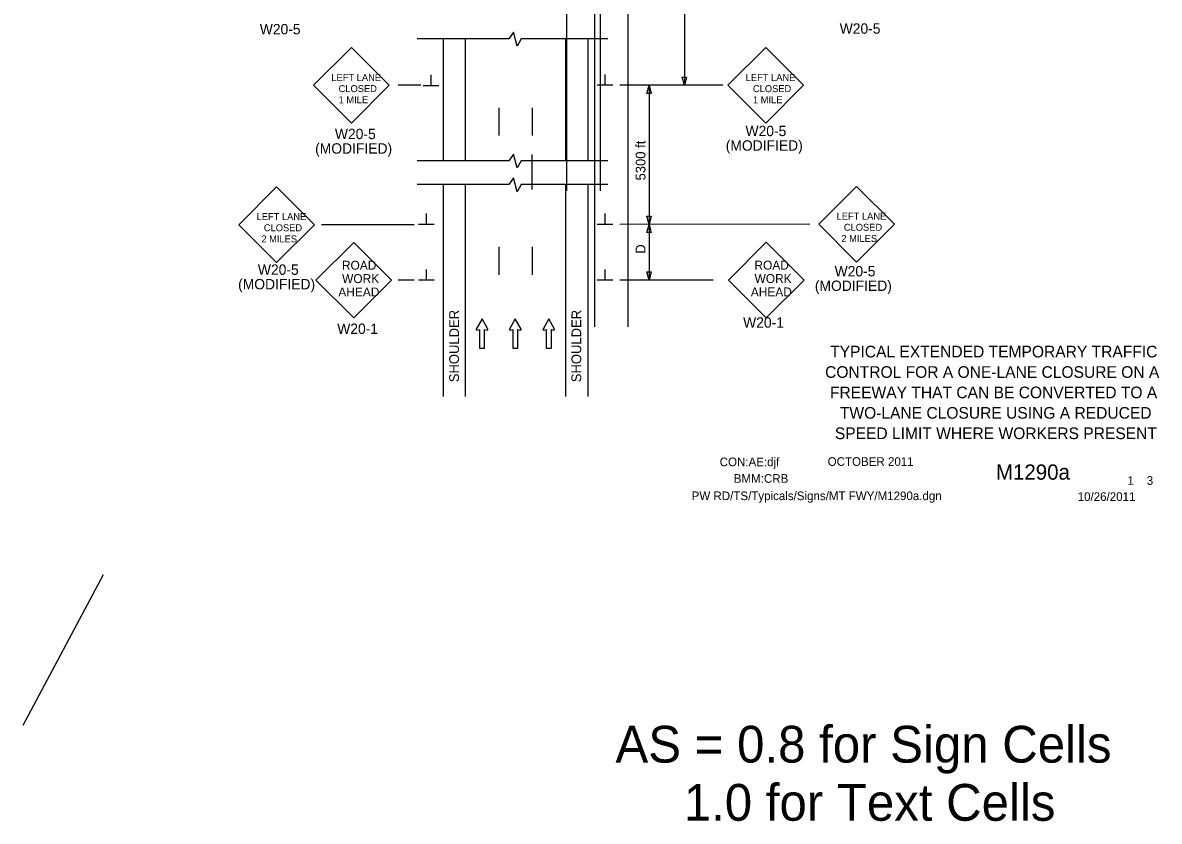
# Model space of a CAD drawing. Extents: x 16590 to 19504, y 5703 to 6974.
# Drawn here: x 16590 to 17407, y 5703 to 6277 of the extents above; entities that cross this region are included whole.
import ezdxf

# ---------------------------------------------------------------- set-up
doc = ezdxf.new("R2010")
doc.units = 0
for name, color, linetype in [('ALI_LEGAL_EX', 7, 'Continuous'), ('BORDER', 7, 'Continuous'), ('BORDER_SIGNAL_WO', 7, 'Continuous'), ('MT_SCRATCH_LEVEL_E', 7, 'Continuous'), ('PAVT_EDGE_EX', 7, 'Continuous'), ('TRAFFIC_SIGNS_PR', 7, 'Continuous'), ('TYPICAL_TEXT_DIMEN_PR', 7, 'Continuous')]:
    doc.layers.add(name, color=color, linetype=linetype)

msp = doc.modelspace()

# ---------------------------------------------------------------- linework, layer by layer
at = {"layer": 'ALI_LEGAL_EX'}
for p, q in [((16980.68, 6974.12), (16980.68, 6155.98)), ((17004.68, 6974.12), (17004.68, 6155.98)), ((17000.61, 6922.21), (17000.61, 6058.3)), ((17024.61, 6922.21), (17024.61, 6058.3))]:
    msp.add_line(p, q, dxfattribs=at)
for points in [[(16931.89, 6215.64), (16931.89, 6195.69)], [(16955.89, 6215.64), (16955.89, 6195.69)], [(16955.89, 6156.97), (16955.89, 6181.97)], [(16931.89, 6115.64), (16931.89, 6095.69)], [(16955.89, 6115.64), (16955.89, 6095.69)]]:
    msp.add_lwpolyline(points, dxfattribs=at)
at = {"layer": 'MT_SCRATCH_LEVEL_E'}
for p, q in [((16919.89, 6063.87), (16915.78, 6056.63)), ((16924.03, 6056.63), (16919.89, 6063.87)), ((16943.79, 6063.87), (16939.68, 6056.63)), ((16947.94, 6056.63), (16943.79, 6063.87)), ((16967.84, 6063.87), (16963.73, 6056.63)), ((16971.99, 6056.63), (16967.84, 6063.87)), ((16916.26, 6055.95), (16918.04, 6056.26)), ((16918.04, 6056.26), (16918.04, 6043.01)), ((16921.78, 6043.01), (16921.78, 6056.26)), ((16921.78, 6056.26), (16923.56, 6055.95)), ((16940.16, 6055.95), (16941.94, 6056.26)), ((16941.94, 6056.26), (16941.94, 6043.01)), ((16945.68, 6043.01), (16945.68, 6056.26)), ((16945.68, 6056.26), (16947.46, 6055.95)), ((16964.22, 6055.95), (16965.99, 6056.26)), ((16965.99, 6056.26), (16965.99, 6043.01)), ((16969.73, 6043.01), (16969.73, 6056.26)), ((16969.73, 6056.26), (16971.51, 6055.95)), ((16918.04, 6043.01), (16921.78, 6043.01)), ((16941.94, 6043.01), (16945.68, 6043.01)), ((16965.99, 6043.01), (16969.73, 6043.01))]:
    msp.add_line(p, q, dxfattribs=at)
for centre, start, end in [((16916.18, 6056.41), 150.42484, 279.96381), ((16923.62, 6056.41), 260.03619, 29.77312), ((16940.09, 6056.41), 150.42484, 279.96381), ((16947.53, 6056.41), 260.03619, 29.77312), ((16964.14, 6056.41), 150.42484, 279.96381), ((16971.58, 6056.41), 260.03619, 29.77312)]:
    msp.add_arc(centre, 0.463, start, end, dxfattribs=at)
at = {"layer": 'PAVT_EDGE_EX'}
for p, q in [((16891.89, 6265.13), (16891.89, 6177.64)), ((16907.89, 6265.13), (16907.89, 6177.64)), ((16979.89, 6265.13), (16979.89, 6177.64)), ((16995.89, 6265.13), (16995.89, 6177.64)), ((16891.89, 6160.5), (16891.89, 6008.06)), ((16907.89, 6160.5), (16907.89, 6008.06)), ((16979.89, 6160.5), (16979.89, 6008.06)), ((16995.89, 6160.5), (16995.89, 6008.06))]:
    msp.add_line(p, q, dxfattribs=at)
at = {"layer": 'TRAFFIC_SIGNS_PR'}
for p, q in [((16826, 6258.98), (16798.81, 6231.79)), ((16853.19, 6231.79), (16826, 6258.98)), ((17123.75, 6258.98), (17096.56, 6231.79)), ((17150.93, 6231.79), (17123.75, 6258.98)), ((16798.81, 6231.79), (16826, 6204.61)), ((16826, 6204.61), (16853.19, 6231.79)), ((17096.56, 6231.79), (17123.75, 6204.61)), ((17123.75, 6204.61), (17150.93, 6231.79)), ((16772.25, 6158.78), (16745.07, 6131.59)), ((16799.44, 6131.59), (16772.25, 6158.78)), ((17189.06, 6159.1), (17161.87, 6131.91)), ((17216.24, 6131.91), (17189.06, 6159.1)), ((16745.07, 6131.59), (16772.25, 6104.4)), ((16772.25, 6104.4), (16799.44, 6131.59)), ((17161.87, 6131.91), (17189.06, 6104.73)), ((17189.06, 6104.73), (17216.24, 6131.91)), ((16827.68, 6118.91), (16800.52, 6091.76)), ((16854.83, 6091.76), (16827.68, 6118.91)), ((17124.1, 6118.98), (17096.92, 6091.79)), ((17151.29, 6091.79), (17124.1, 6118.98)), ((16800.52, 6091.76), (16827.68, 6064.61)), ((16827.68, 6064.61), (16854.83, 6091.76)), ((17096.92, 6091.79), (17124.1, 6064.61)), ((17124.1, 6064.61), (17151.29, 6091.79))]:
    msp.add_line(p, q, dxfattribs=at)
at = {"layer": 'TYPICAL_TEXT_DIMEN_PR'}
for p, q in [((17065.33, 6507.47), (17065.33, 6231.79)), ((16939.24, 6265.13), (16873.3, 6265.13)), ((16942.49, 6269.93), (16939.24, 6265.13)), ((16945.23, 6259.99), (16942.49, 6269.93)), ((16947.98, 6265.13), (16945.23, 6259.99)), ((17010.31, 6265.13), (16947.98, 6265.13)), ((16875.9, 6231.79), (16859.74, 6231.79)), ((16883.26, 6231.53), (16883.26, 6239.32)), ((17013.89, 6231.79), (17002.64, 6231.79)), ((17008.26, 6231.79), (17008.26, 6239.58)), ((17093.01, 6231.79), (17018.89, 6231.79)), ((17038.32, 6225.93), (17039.89, 6231.79)), ((17039.89, 6231.79), (17039.89, 6131.79)), ((17039.89, 6231.79), (17041.46, 6225.93)), ((17065.33, 6231.79), (17063.75, 6237.65)), ((17063.75, 6237.65), (17065.33, 6237.65)), ((17065.33, 6237.65), (17066.9, 6237.65)), ((17066.9, 6237.65), (17065.33, 6231.79)), ((16888.89, 6231.53), (16877.64, 6231.53)), ((17039.89, 6225.93), (17038.32, 6225.93)), ((17041.46, 6225.93), (17039.89, 6225.93)), ((16939.24, 6177.64), (16873.3, 6177.64)), ((16942.49, 6182.44), (16939.24, 6177.64)), ((16945.23, 6172.5), (16942.49, 6182.44)), ((16947.98, 6177.64), (16945.23, 6172.5)), ((17010.31, 6177.64), (16947.98, 6177.64)), ((16939.24, 6160.5), (16873.3, 6160.5)), ((16942.49, 6165.3), (16939.24, 6160.5)), ((16945.23, 6155.36), (16942.49, 6165.3)), ((16947.98, 6160.5), (16945.23, 6155.36)), ((17010.31, 6160.5), (16947.98, 6160.5)), ((16879.93, 6131.79), (16879.93, 6139.58)), ((17008.26, 6131.79), (17008.26, 6139.58)), ((17039.89, 6131.79), (17038.32, 6137.65)), ((17038.32, 6137.65), (17039.89, 6137.65)), ((17039.89, 6137.65), (17041.46, 6137.65)), ((17041.46, 6137.65), (17039.89, 6131.79)), ((16871.22, 6131.59), (16804.48, 6131.5)), ((16885.56, 6131.79), (16874.31, 6131.79)), ((17013.89, 6131.79), (17002.64, 6131.79)), ((17155.46, 6131.98), (17019.03, 6131.79)), ((17038.32, 6125.93), (17039.89, 6131.79)), ((17039.89, 6125.93), (17038.32, 6125.93)), ((17039.89, 6131.79), (17039.89, 6091.79)), ((17039.89, 6131.79), (17041.46, 6125.93)), ((17041.46, 6125.93), (17039.89, 6125.93)), ((16879.93, 6091.74), (16879.93, 6099.53)), ((17008.26, 6091.74), (17008.26, 6099.53)), ((17039.89, 6091.79), (17038.32, 6097.65)), ((17038.32, 6097.65), (17039.89, 6097.65)), ((17039.89, 6097.65), (17041.46, 6097.65)), ((17041.46, 6097.65), (17039.89, 6091.79)), ((16871.09, 6091.79), (16859.74, 6091.79)), ((16885.56, 6091.74), (16874.31, 6091.74)), ((17013.89, 6091.74), (17002.64, 6091.74)), ((17086.1, 6091.79), (17018.89, 6091.79)), ((16647.75, 5880), (16589.83, 5771.74))]:
    msp.add_line(p, q, dxfattribs=at)

# ---------------------------------------------------------------- texts
at = {"layer": 'BORDER'}
for s, p in [('TYPICAL EXTENDED TEMPORARY TRAFFIC', (17170.06, 6036.26)), ('CONTROL FOR A ONE-LANE CLOSURE ON A', (17166.43, 6021.58)), ('FREEWAY THAT CAN BE CONVERTED TO A', (17169.93, 6006.91)), ('TWO-LANE CLOSURE USING A REDUCED', (17177.04, 5992.23)), ('SPEED LIMIT WHERE WORKERS PRESENT', (17173.43, 5977.56))]:
    msp.add_text(s, height=8.3734, dxfattribs=at).set_placement(p)
at = {"layer": 'BORDER_SIGNAL_WO'}
for s, height, p in [('CON:AE:djf  ', 6.2, (17090.69, 5958.06)), ('    OCTOBER 2011    ', 6.2, (17159.08, 5958.34)), ('    M1290a   ', 11, (17272.86, 5948.38)), ('BMM:CRB   ', 6.2, (17100.81, 5946.17)), (' 1    3 ', 6.2, (17381.45, 5944.7)), ('PW RD/TS/Typicals/Signs/MT FWY/M1290a.dgn      ', 6.2, (17070.55, 5933.71)), ('10/26/2011    ', 6.2, (17347.93, 5933.13)), ('AS = 0.8 for Sign Cells', 26.4241, (17015.79, 5745.09)), ('     1.0 for Text Cells', 26.4241, (17015.79, 5703.3))]:
    msp.add_text(s, height=height, dxfattribs=at).set_placement(p)
at = {"layer": 'TRAFFIC_SIGNS_PR'}
for s, height, p in [('W20-5', 7.44, (16760.18, 6268.43)), ('W20-5', 7.44, (17176.92, 6268.88)), ('LEFT LANE', 5.006, (16811.61, 6234.92)), ('LEFT LANE', 5.006, (17109.36, 6234.92)), ('CLOSED', 5.006, (16816.82, 6226.91)), ('CLOSED', 5.006, (17114.57, 6226.91)), ('1 MILE', 5.006, (16816.82, 6218.9)), ('1 MILE', 5.006, (17114.57, 6218.9)), ('W20-5', 7.449, (16814.16, 6193.15)), ('W20-5', 7.449, (17109.22, 6195.29)), ('(MODIFIED)', 7.449, (17095.03, 6184.84)), ('(MODIFIED)', 7.449, (16799.96, 6182.7)), ('LEFT LANE', 5.006, (16757.86, 6134.94)), ('LEFT LANE', 5.006, (17174.67, 6135.27)), ('CLOSED', 5.006, (16763.08, 6126.93)), ('CLOSED', 5.006, (17179.88, 6127.26)), ('2 MILES', 5.006, (16761.33, 6118.92)), ('2 MILES', 5.006, (17178.13, 6119.25)), ('W20-5', 7.449, (16758.81, 6095.62)), ('ROAD', 6.4, (16819.22, 6099.29)), ('ROAD', 6.408, (17115.63, 6099.34)), ('W20-5', 7.449, (17173.26, 6094.48)), ('(MODIFIED)', 7.449, (16744.61, 6085.17)), ('WORK', 6.4, (16819.33, 6089.69)), ('WORK', 6.408, (17115.74, 6089.73)), ('AHEAD', 6.4, (16816.64, 6080.09)), ('AHEAD', 6.408, (17113.05, 6080.11)), ('(MODIFIED)', 7.449, (17159.07, 6084.03)), ('W20-1', 7.44, (16815.85, 6053.17)), ('W20-1', 7.449, (17107.51, 6057.64))]:
    msp.add_text(s, height=height, dxfattribs=at).set_placement(p)
at = {"layer": 'TYPICAL_TEXT_DIMEN_PR'}
for s, p in [('5300 ft', (17037.33, 6163.4)), ('D', (17037.33, 6110.8)), ('SHOULDER', (16903.31, 6018.42)), ('SHOULDER', (16991.17, 6018.42))]:
    msp.add_text(s, height=7, rotation=90, dxfattribs=at).set_placement(p)

doc.saveas('drawing.dxf')
